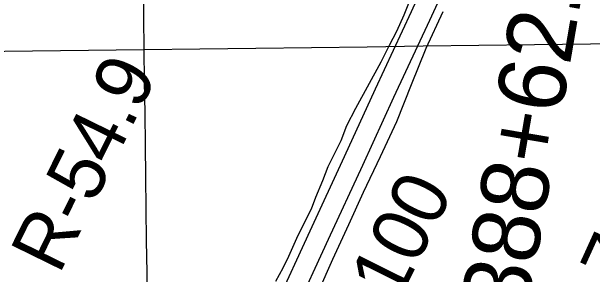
# Model space of a CAD drawing. Extents: x 3734862 to 3772949, y 391520 to 417239.
# Drawn here: x 3741360 to 3742221, y 408673 to 409063 of the extents above; entities that cross this region are included whole.
import ezdxf

# ---------------------------------------------------------------- set-up
doc = ezdxf.new("R2010")
doc.units = 0
for name, color, linetype in [('V-GRID-MAJR', 7, 'Continuous'), ('V-RIVR-RANG-IDEN', 7, 'Continuous'), ('V-ROAD-CNTR', 7, 'Continuous'), ('V-SITE-VEGE', 7, 'Continuous'), ('V-SURV-IDEN', 7, 'Continuous')]:
    doc.layers.add(name, color=color, linetype=linetype)

msp = doc.modelspace()

# ---------------------------------------------------------------- linework, layer by layer
at = {"layer": 'V-GRID-MAJR'}
for points in [[(3741709.628, 396887.316), (3741632.95, 402946.574), (3741556.258, 409006.89400000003), (3741479.5670000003, 415067.217), (3741479.554, 415068.275)], [(3738908.566, 408973.485), (3741556.258, 409006.89400000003), (3746851.637, 409074.29000000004), (3752147.005, 409142.456), (3757442.364, 409211.393), (3762737.7120000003, 409281.10000000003), (3768033.0500000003, 409351.577), (3770680.715, 409387.104)]]:
    msp.add_spline(points, degree=3, dxfattribs=at)
at = {"layer": 'V-ROAD-CNTR'}
for points in [[(3741692.6233325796, 408489.74363223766), (3741693.2772389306, 408492.045513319), (3741695.9630441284, 408500.7619267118), (3741698.840916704, 408509.41526300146), (3741702.05726126, 408518.41580500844), (3741718.5689345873, 408554.979109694), (3741735.02763571, 408590.9393727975), (3741751.641253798, 408626.75417248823), (3741802.5522428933, 408737.652365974), (3741853.1959602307, 408847.74888177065), (3741899.205737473, 408948.41802630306), (3741952.585300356, 409063.1242358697), (3742010.331281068, 409189.4127065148), (3742072.735830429, 409326.25786089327), (3742124.7849146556, 409442.0943332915), (3742189.1470783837, 409580.94240530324), (3742253.4802625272, 409720.53129551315), (3742308.771171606, 409840.09096228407), (3742388.711897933, 410014.5776341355), (3742473.8403317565, 410199.3201933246), (3742557.8918733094, 410384.89351832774), (3742657.291548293, 410602.167595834)], [(3741721.326470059, 408480.99995872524), (3741722.0447610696, 408483.528486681), (3741724.5349558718, 408491.6100732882), (3741727.2030832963, 408499.63273699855), (3741729.89873874, 408507.1761949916), (3741745.879065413, 408542.562890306), (3741762.2743642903, 408578.3846272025), (3741778.8807462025, 408614.1838275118), (3741829.811757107, 408725.1256340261), (3741880.46603977, 408835.2451182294), (3741926.448262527, 408935.85397369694), (3741979.8266996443, 409050.55776413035), (3742037.6207189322, 409176.9512934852), (3742100.066169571, 409313.88613910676), (3742152.0770853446, 409429.6376667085), (3742216.378921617, 409568.35559469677), (3742280.717737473, 409707.95670448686), (3742336.022828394, 409827.5470377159), (3742415.972102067, 410002.0523658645), (3742501.1276682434, 410186.85380667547), (3742585.196126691, 410372.4644816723), (3742684.566451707, 410589.674404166)]]:
    msp.add_lwpolyline(points, dxfattribs=at)
at = {"layer": 'V-SITE-VEGE'}
for points in [[(3741949.3680000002, 409077.507), (3741941.6180000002, 409057.688), (3741930.569, 409033.819), (3741919.5300000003, 409012.766), (3741907.384, 408987.966), (3741869.713, 408919.197), (3741856.153, 408893.621), (3741847.7660000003, 408871.148), (3741828.8370000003, 408832.777), (3741820.768, 408811.554), (3741810.497, 408787.058), (3741804.167, 408769.889), (3741794.074, 408750.552), (3741782.083, 408725.906), (3741770.239, 408699.54000000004), (3741762.031, 408681.911), (3741751.156, 408661.953)], [(3741814.863, 408647.13), (3741836.029, 408695.496), (3741859.7060000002, 408746.663), (3741881.497, 408795.02400000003), (3741906.7490000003, 408848.059), (3741931.057, 408900.162), (3741952.565, 408955.092), (3741974.382, 409009.081), (3741999.947, 409063.368)]]:
    msp.add_lwpolyline(points, dxfattribs=at)

# ---------------------------------------------------------------- texts
at = {"layer": 'V-RIVR-RANG-IDEN'}
for s, height, rotation, p in [('R-54.9', 82.99999800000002, 63.86935423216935, (3741430.092020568, 408671.19245686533)), ('D-100', 83.00000000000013, 63.584325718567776, (3741880.6775922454, 408524.9578142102)), ('R-54.7', 82.99999799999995, 65.54442589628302, (3742163.8713151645, 408403.959215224))]:
    msp.add_text(s, height=height, rotation=rotation, dxfattribs=at).set_placement(p)
at = {"layer": 'V-SURV-IDEN'}
msp.add_text('1388+62.9', height=100, rotation=80.2897222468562, dxfattribs=at).set_placement((3742111.6254817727, 408538.526473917))

doc.saveas('drawing.dxf')
